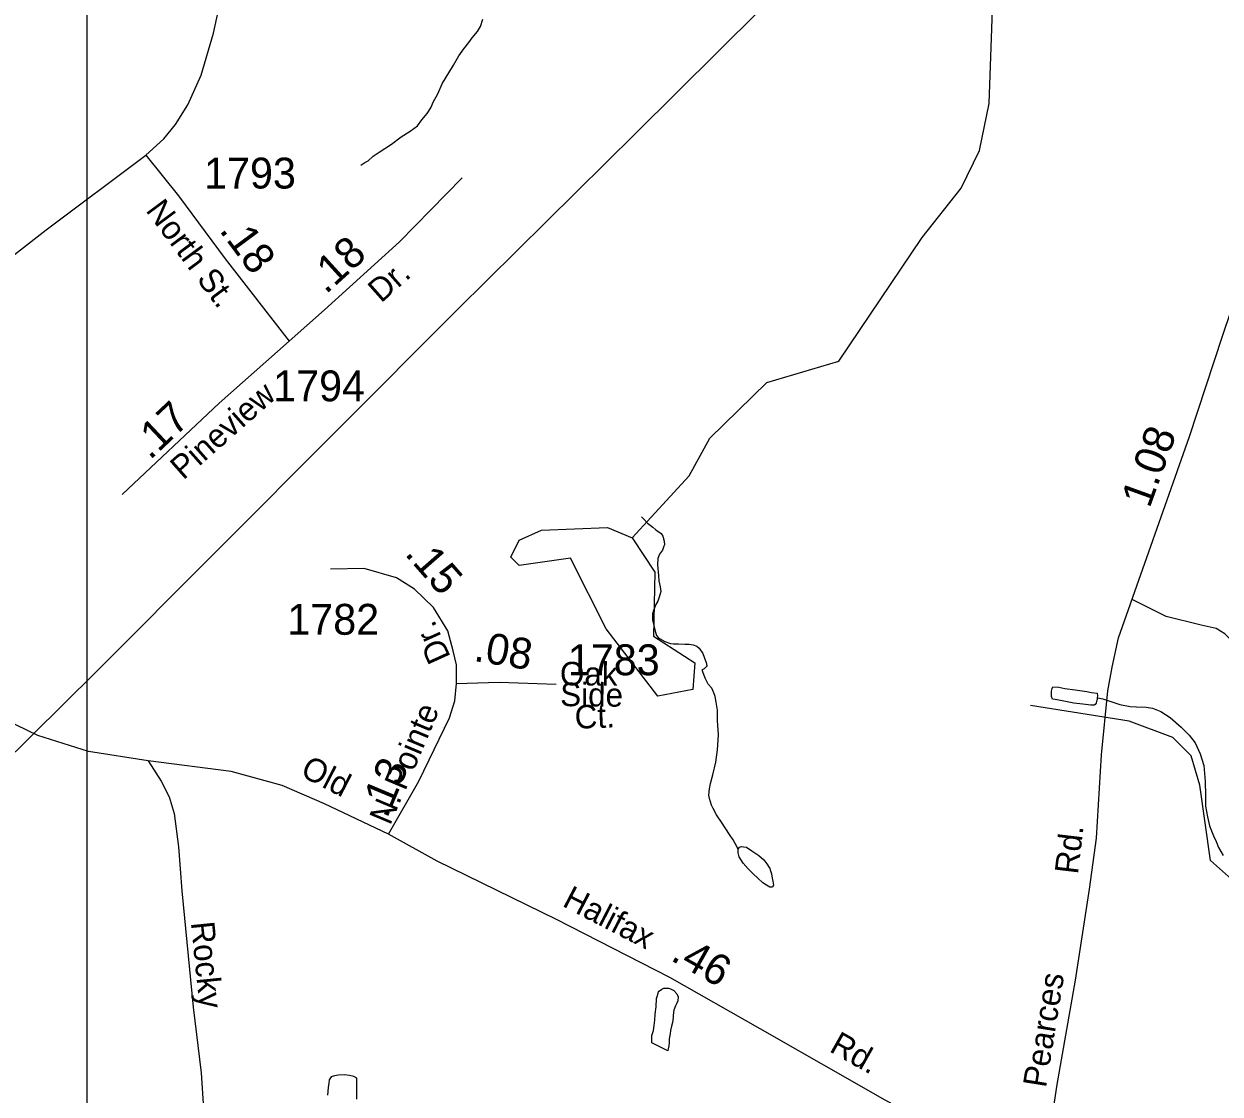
# Model space of a CAD drawing. Extents: x 2126262 to 2293712, y 749403 to 919119.
# Drawn here: x 2205182 to 2210024, y 798331 to 802665 of the extents above; entities that cross this region are included whole.
import ezdxf

# ---------------------------------------------------------------- set-up
doc = ezdxf.new("R2010")
doc.units = 0
for name, color, linetype in [('Exist Hydrographic Misc Water Feature', 7, 'Continuous'), ('Exist Hydrographic Pond Under 1500 Sq Ft', 7, 'Continuous'), ('Exist Road Non-System Type 51', 7, 'Continuous'), ('Exist Road Non-System Type 51 Label', 7, 'Continuous'), ('Exist Road Secondary Mileage Hundredths English Label', 7, 'Continuous'), ('Exist Road Secondary Type 51 Attributed', 7, 'Continuous'), ('Exist Road Secondary Type 51 Label', 7, 'Continuous'), ('Exist Road Secondary Type 51 Number Label', 7, 'Continuous'), ('Exist Utilities Electrical Transmission Line', 7, 'Continuous'), ('Map Preparation Inset Cut Line', 7, 'Continuous')]:
    doc.layers.add(name, color=color, linetype=linetype)

msp = doc.modelspace()

# ---------------------------------------------------------------- linework, layer by layer
at = {"layer": 'Exist Hydrographic Misc Water Feature'}
for points in [[(2207644.4, 800584), (2207875.5, 800835.2), (2207958.4, 800987.6), (2208189.5, 801212.5), (2208480.4, 801298.3), (2208818.6, 801799.8), (2208975.4, 802000), (2209049.5, 802152.6), (2209089.4, 802342), (2209110.6, 802951.7), (2209159.6, 803059), (2209242.4, 803119.6)], [(2206546.2, 802092.6), (2206562.2, 802102.8), (2206576.1, 802110.8), (2206596, 802129), (2206620, 802145.1), (2206669.6, 802177.5), (2206709.4, 802207.7), (2206745.3, 802230), (2206775, 802252.2), (2206792.9, 802276.3), (2206814.8, 802302.4), (2206828.6, 802324.6), (2206840.4, 802350.6), (2206856.2, 802378.6), (2206875.9, 802424.8), (2206901.5, 802467), (2206921.4, 802497.1), (2206943, 802535.3), (2206963.1, 802563.3), (2206982.7, 802589.5), (2206996.5, 802607.6), (2207018.4, 802633.7), (2207030.3, 802653.8), (2207040, 802683.9)], [(2207681.8, 800669), (2207691.6, 800659), (2207705.8, 800643.1), (2207727.9, 800627.3), (2207740, 800615.4), (2207761.9, 800601.5), (2207768.3, 800589.6), (2207774.3, 800569.7), (2207774.5, 800555.7), (2207772.4, 800549.7), (2207766.5, 800533.6), (2207754.8, 800517.5), (2207748.6, 800499.5), (2207747, 800473.5), (2207751.3, 800431.5), (2207751.5, 800409.5), (2207757.4, 800385.6), (2207759.7, 800365.6), (2207754, 800343.6), (2207748, 800327.5), (2207740, 800313.5), (2207730.2, 800289.5), (2207726.3, 800275.4), (2207726.5, 800249.5), (2207732.6, 800223.4), (2207736.7, 800205.5), (2207742.9, 800187.6), (2207749, 800179.6), (2207755, 800175.7), (2207776.9, 800163.8), (2207799.3, 800156), (2207811.2, 800154), (2207831.3, 800154.2), (2207857.3, 800152.3), (2207875.1, 800152.4), (2207891.1, 800150.6), (2207905.3, 800144.7), (2207915.1, 800136.8), (2207929.5, 800114.9), (2207941.4, 800085), (2207943.6, 800079), (2207945.7, 800065), (2207943.6, 800061), (2207939.7, 800056.9), (2207935.6, 800052.9), (2207927.6, 800048.9)], [(2208072.6, 799322.1), (2208060.7, 799346.1), (2208052.5, 799360), (2208038.4, 799381.9), (2208006, 799431.6), (2207985.9, 799461.5), (2207971.7, 799487.4), (2207965.4, 799501.4), (2207957.4, 799527.3), (2207955.1, 799541.3), (2207957.2, 799567.3), (2207960.8, 799589.3), (2207970.7, 799623.4), (2207982.4, 799675.4), (2207990, 799725.5), (2207993.7, 799785.5), (2207989.1, 799843.4), (2207988.9, 799885.3), (2207984.6, 799917.4), (2207980.5, 799941.3), (2207974.4, 799955.2), (2207966.2, 799975.2), (2207952.2, 799991.1), (2207939.9, 800015), (2207929.9, 800040.9), (2207927.6, 800048.9)], [(2209526, 799935.9), (2209526, 799927.9), (2209524.2, 799921.9), (2209522.1, 799913.9), (2209518.2, 799907.9), (2209514.1, 799905.9), (2209500.2, 799905.8), (2209468.2, 799909.6), (2209432.1, 799913.3), (2209398.3, 799921), (2209378.2, 799924.9), (2209356.2, 799928.8), (2209346.2, 799930.7), (2209341.9, 799940.7), (2209341.9, 799954.7), (2209341.9, 799962.7), (2209343.7, 799972.7), (2209347.6, 799980.7), (2209371.6, 799978.9), (2209395.6, 799973), (2209437.6, 799967.3), (2209484, 799961.6), (2209503.9, 799957.8), (2209526, 799953.9), (2209527.9, 799944), (2209526, 799935.9)], [(2209526, 799935.9), (2209535.9, 799934), (2209550, 799932.1), (2209578.1, 799922.3), (2209618.3, 799908.6), (2209660.1, 799900.8), (2209686.2, 799899.1), (2209724.3, 799897.3), (2209750.1, 799893.5), (2209784.2, 799879.7), (2209822.5, 799856), (2209866.6, 799816.4), (2209899, 799784.5), (2209923.2, 799752.7), (2209943.5, 799708.9), (2209957.6, 799661), (2209964.2, 799597.1), (2209964.4, 799541.1), (2209965, 799497.1), (2209973.2, 799453.2), (2209981.4, 799417.3), (2209997.6, 799377.4), (2210007.9, 799353.5), (2210017.9, 799329.5), (2210036.2, 799297.7)], [(2213880.4, 798569.4), (2213805.4, 798603.7), (2213779.4, 798686.2), (2213578.4, 798884), (2213286.4, 799040.9), (2212676.4, 799210.8), (2212568.3, 799275.4), (2212408.4, 799449.3), (2211884.5, 799381.3), (2211309.5, 799376.8), (2211018.3, 799323.8), (2210686.4, 799156.7), (2210511.5, 799104.6), (2210253.5, 799119.7), (2210119.4, 799158.5), (2209985.5, 799276.2), (2209941.4, 799582.1), (2209907.4, 799700.9), (2209832.5, 799774.6), (2209656.4, 799840.5), (2209256.5, 799904.6)], [(2208072.6, 799322.1), (2208078.8, 799330.2), (2208086.8, 799334.2), (2208094.7, 799332.3), (2208106.6, 799330.4), (2208128.8, 799316.5), (2208156.9, 799296.7), (2208177, 799278.9), (2208189.3, 799263), (2208199.1, 799249), (2208201.2, 799245.1), (2208203.2, 799239.1), (2208207.5, 799223.1), (2208211.4, 799205.2), (2208213.7, 799193.2), (2208215.7, 799177.2), (2208213.7, 799173.2), (2208211.6, 799169.2), (2208205.7, 799169.2), (2208201.8, 799169.1), (2208187.6, 799177), (2208173.7, 799186.9), (2208153.4, 799204.7), (2208133.5, 799222.6), (2208113.2, 799242.5), (2208093.1, 799266.3), (2208076.9, 799292.2), (2208073, 799308.1), (2208072.6, 799322.1)], [(2207819.2, 798688.6), (2207813.4, 798670.6), (2207809.5, 798650.6), (2207809.5, 798640.6), (2207807.7, 798620.6), (2207803.8, 798606.6), (2207799.9, 798588.5), (2207798, 798574.5), (2207794.1, 798554.5), (2207794.1, 798540.5), (2207792.5, 798526.5), (2207790.4, 798514.5), (2207788.4, 798506.4), (2207724.2, 798538), (2207724.2, 798554), (2207724, 798568), (2207725.9, 798576), (2207730, 798588.1), (2207733.7, 798608.1), (2207735.7, 798630.1), (2207737.3, 798654.1), (2207741.2, 798684.1), (2207742.9, 798718.1), (2207744.9, 798726.1), (2207749, 798740.1), (2207750.9, 798746.1), (2207764.6, 798756.2), (2207772.6, 798760.2), (2207790.7, 798760.4), (2207798.7, 798756.5), (2207812.6, 798750.6), (2207824.9, 798736.6), (2207830.8, 798724.7), (2207829, 798708.7), (2207823.3, 798696.6), (2207819.2, 798688.6)], [(2206530.2, 798309.8), (2206530.2, 798335.9), (2206530, 798353.9), (2206530, 798371.9), (2206529.6, 798383.9), (2206529.6, 798395.8), (2206517.7, 798401.8), (2206499.6, 798405.6), (2206479.8, 798409.5), (2206455.8, 798407.3), (2206439.8, 798405.2), (2206425.6, 798401.1), (2206417.6, 798389), (2206416, 798375.1), (2206413.9, 798357.1), (2206410.2, 798327.1)]]:
    msp.add_lwpolyline(points, dxfattribs=at)
at = {"layer": 'Exist Hydrographic Pond Under 1500 Sq Ft'}
msp.add_lwpolyline([(2207644.4, 800584), (2207736.5, 800444.4), (2207730.6, 800185.3), (2207897.5, 800076.9), (2207889.5, 799968.8), (2207748.4, 799942.2), (2207538.4, 800215.5), (2207394.5, 800500.6), (2207186.6, 800472.1), (2207153.5, 800505.6), (2207186.6, 800573.8), (2207277.4, 800614.6), (2207544.4, 800625.5), (2207644.4, 800584)], dxfattribs=at)
at = {"layer": 'Exist Road Non-System Type 51'}
msp.add_line((2206876.9, 799814.1), (2206877, 799814.2), dxfattribs=at)
for points in [[(2210206.4, 800106.2), (2210180, 800128.2), (2210114.1, 800137), (2210074.5, 800163.4), (2210043.7, 800194.2), (2210008.6, 800216.2), (2209947, 800229.4), (2209806.4, 800264.5), (2209667.7, 800333.9)], [(2205685.3, 799681), (2205737.1, 799598.6), (2205770.1, 799534.9), (2205789.9, 799466.7), (2205807.5, 799332.5), (2205820.6, 799154.4), (2205866.8, 798682.5), (2205899.8, 798416.4), (2205908.6, 798271.2), (2205937.1, 797900.9), (2205952.5, 797661.2), (2205996.5, 797015.1), (2206016.3, 796872.1)]]:
    msp.add_lwpolyline(points, dxfattribs=at)
at = {"layer": 'Exist Road Secondary Type 51 Attributed'}
for points in [[(2205675.3, 802132.6), (2205748.1, 802199.7), (2205795.5, 802256.9), (2205845.7, 802336.5), (2205898.8, 802456.7), (2205949.7, 802627.7), (2206156.9, 803582.3), (2206202.3, 803756.2), (2206288.8, 803926.6), (2206408.8, 804101.2), (2206750, 804554.4), (2207068.8, 804961.5), (2207241.8, 805164.9), (2207315.1, 805242.9), (2207405.8, 805305.8), (2207527.2, 805360.2), (2207642.4, 805387.5), (2208499.8, 805480.3), (2208799.9, 805522.2), (2209168.9, 805622.1), (2209696.8, 805772.4), (2209705.4, 805776.1), (2209761.8, 805784.5)], [(2209286.9, 797956.2), (2209307.4, 798030.5), (2209326.6, 798118.8), (2209365, 798369.5), (2209438.2, 798792), (2209494.8, 799161.4), (2209524.1, 799366.7), (2209544.3, 799705.4), (2209569.4, 799963.7), (2209587.7, 800059.6), (2209612.8, 800178.3), (2209900.3, 800993.9), (2210033.6, 801399.6), (2210283.3, 802139.9), (2210374, 802403.8), (2210410.3, 802514.2), (2210459.2, 802698.5), (2210503.1, 802880.8), (2210507.3, 803002.3), (2210503.1, 803139.1), (2210485.7, 803282.3), (2210466.8, 803482.7)], [(2203927.8, 800702.6), (2203984.9, 800798.2), (2204078.4, 800902.9), (2204181, 801000), (2204351.2, 801139.6), (2204554.3, 801285.6), (2204837.5, 801493.7), (2205272.2, 801831), (2205675.3, 802132.6)], [(2205675.3, 802132.6), (2205807.8, 801968.4), (2205996.9, 801713.6), (2206256.2, 801380.4)], [(2206256.2, 801380.4), (2206399.2, 801506.8), (2206702.7, 801782.6), (2206955.4, 802041.4)], [(2205579.2, 800758.4), (2205972, 801129.2), (2206256.2, 801380.4)], [(2206657.9, 799383.5), (2206399.1, 799505.7), (2206227.4, 799581.2), (2206020.9, 799637), (2205685.3, 799681), (2205443.9, 799718.7), (2205238.8, 799783), (2204886.4, 799952.7), (2204670.1, 800096.5), (2204559.9, 800188.7), (2204428, 800350), (2204295.5, 800495.2), (2204198.5, 800585.3), (2204113.4, 800635.6), (2204025.5, 800671.9), (2203927.8, 800702.6)], [(2206932.6, 799994.2), (2206932.6, 800069.7), (2206920, 800125.5), (2206897.7, 800206.5), (2206839.3, 800302), (2206762.5, 800376), (2206690.1, 800422), (2206558.9, 800459.8), (2206423.6, 800457)], [(2206657.9, 799383.5), (2206780, 799598.6), (2206904.9, 799854.8), (2206925.8, 799923.3), (2206932.6, 799994.2)], [(2206932.6, 799994.2), (2207105.6, 799998.4), (2207335.9, 799991.4)], [(2208782.4, 798244.6), (2208668.7, 798306.7), (2208162.2, 798595.8), (2207796.6, 798802.5), (2207337.5, 799038.6), (2206854.7, 799274.6), (2206657.9, 799383.5)]]:
    msp.add_lwpolyline(points, dxfattribs=at)
at = {"layer": 'Exist Utilities Electrical Transmission Line'}
msp.add_lwpolyline([(2208159.2, 802719.4), (2207658.2, 802220.8), (2206937.7, 801507.8), (2205472.6, 800039.6), (2204953.7, 799526.8)], dxfattribs=at)
at = {"layer": 'Map Preparation Inset Cut Line'}
msp.add_lwpolyline([(2224442, 807770.9), (2205436.6, 807770.9), (2205436.6, 794867.7), (2224442, 794867.7)], close=True, dxfattribs=at)

# ---------------------------------------------------------------- texts
at = {"layer": 'Exist Road Non-System Type 51 Label'}
msp.add_text('Rocky', height=95, rotation=275.8189, dxfattribs=at).set_placement((2205857.6, 799025.5))
at = {"layer": 'Exist Road Secondary Mileage Hundredths English Label'}
for s, rotation, p in [('.18', 306.5692, (2205970, 801828.4)), ('.18', 42.2653, (2206403.9, 801567.3)), ('.17', 43.3489, (2205692.2, 800895.7)), ('1.08', 70.1314, (2209738.4, 800700.3)), ('.15', 311.1638, (2206720.3, 800517.3)), ('.08', 350.6279, (2206999.3, 800085.4)), ('.13', 67.1816, (2206651.3, 799443.7)), ('.46', 330.5175, (2207795.2, 798875.1))]:
    msp.add_text(s, height=125, rotation=rotation, dxfattribs=at).set_placement(p)
at = {"layer": 'Exist Road Secondary Type 51 Label'}
for s, rotation, p in [('North St.', 306.5692, (2205672.3, 801909.1)), ('Dr.', 41.4665, (2206627.6, 801532)), ('Pineview', 41.4665, (2205827, 800815)), ('Dr.', 114.3504, (2206910.7, 800101.1)), ('Oak', 359.3944, (2207351.5, 799986.8)), ('Side', 359.3944, (2207352.5, 799902.1)), ('Pointe', 67.1816, (2206725.5, 799555.9)), ('Ct.', 2.0351, (2207413, 799810.3)), ('Old', 332.6959, (2206296.4, 799621.7)), ('N.', 67.1816, (2206664.5, 799416.1)), ('Rd.', 83.2266, (2209448.5, 799218.6)), ('Halifax', 332.5482, (2207357.3, 799094.2)), ('Pearces', 80.8393, (2209319.2, 798354)), ('Rd.', 330.641, (2208438.1, 798505.6))]:
    msp.add_text(s, height=95, rotation=rotation, dxfattribs=at).set_placement(p)
at = {"layer": 'Exist Road Secondary Type 51 Number Label'}
for s, p in [('1793', (2205911.1, 801998)), ('1794', (2206190.9, 801136.3)), ('1782', (2206248, 800191)), ('1783', (2207383.7, 800027.1))]:
    msp.add_text(s, height=125, dxfattribs=at).set_placement(p)

doc.saveas('drawing.dxf')
